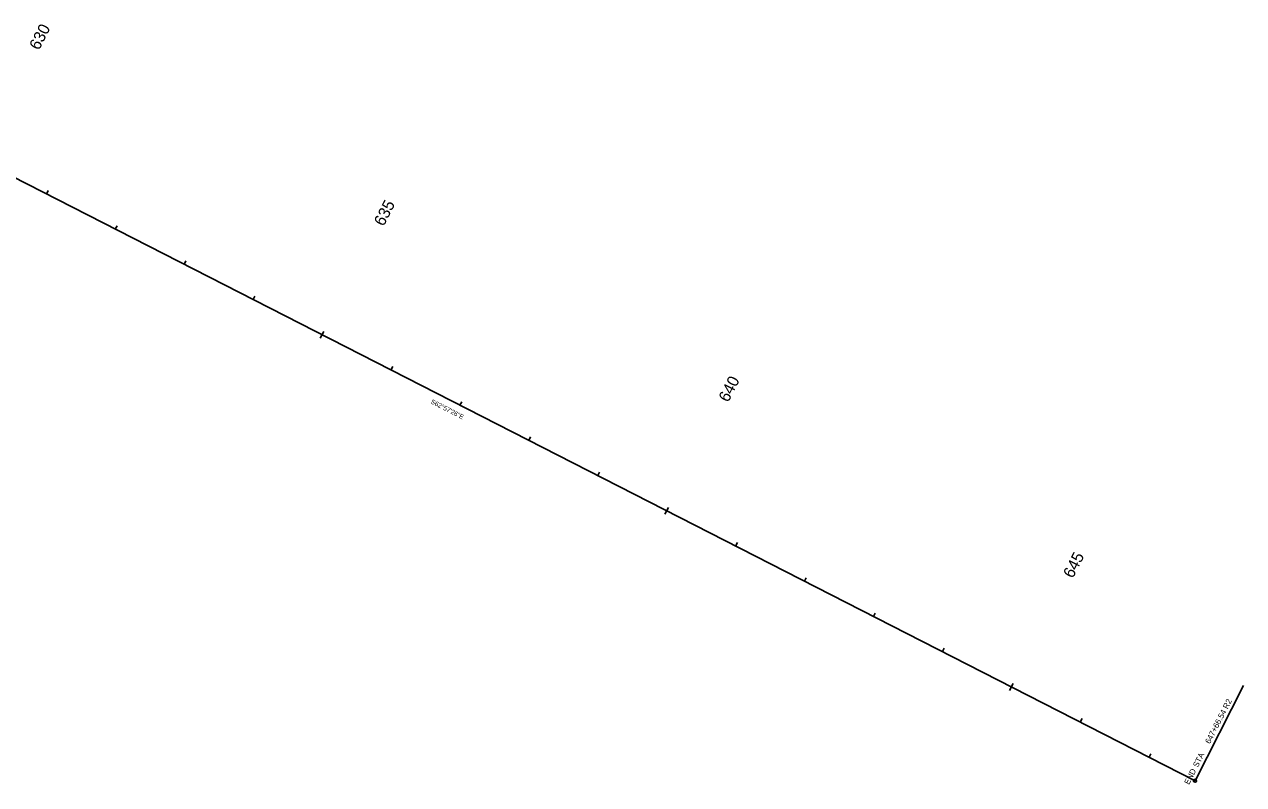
# Model space of a CAD drawing. Extents: x 1604865 to 1608475, y 865355 to 868094.
# Drawn here: x 1606900 to 1608475, y 865355 to 866336 of the extents above; entities that cross this region are included whole.
import ezdxf

# ---------------------------------------------------------------- set-up
doc = ezdxf.new("R2010")
doc.units = 0
for name, color, linetype in [('Default', 7, 'Continuous'), ('Modeling-Contours-Major-Existing', 7, 'Continuous'), ('Modeling-Contours-Minor-Existing', 7, 'Continuous'), ('Modeling-Flow Arrows-Existing', 7, 'Continuous'), ('Modeling-Low Points-Existing', 7, 'Continuous'), ('Modeling-Spot-Existing', 7, 'Continuous'), ('Modeling-Terrain-Existing', 7, 'Continuous'), ('Modeling-Triangle Verticies-Existing', 7, 'Continuous')]:
    doc.layers.add(name, color=color, linetype=linetype)

msp = doc.modelspace()

# ---------------------------------------------------------------- linework, layer by layer
at = {"layer": 'Default'}
msp.add_line((1606506.8, 866332.4), (1608412.4, 865359.6), dxfattribs=at)
at = {"layer": 'Modeling-Contours-Minor-Existing'}
for p, q in [((1607286.6, 865939.9), (1607282.1, 865931)), ((1607732, 865712.6), (1607727.4, 865703.7)), ((1608177.3, 865485.2), (1608172.7, 865476.3))]:
    msp.add_line(p, q, dxfattribs=at)
at = {"layer": 'Modeling-Spot-Existing'}
for p in [(1608412.4, 865359.6), (1608475.2, 865482.5)]:
    msp.add_line(p, (1608475.2, 865482.5), dxfattribs=at)
msp.add_circle((1608412.4, 865359.6), 1.98, dxfattribs=at)
at = {"layer": 'Modeling-Terrain-Existing'}
msp.add_line((1606506.8, 866332.4), (1608412.4, 865359.6), dxfattribs=at)
at = {"layer": 'Modeling-Triangle Verticies-Existing'}
for p, q in [((1606928.1, 866117.3), (1606930.4, 866121.8)), ((1607017.2, 866071.9), (1607019.4, 866076.3)), ((1607106.2, 866026.4), (1607108.5, 866030.8)), ((1607195.3, 865980.9), (1607197.6, 865985.4)), ((1607373.4, 865890), (1607375.7, 865894.4)), ((1607462.5, 865844.5), (1607464.8, 865849)), ((1607551.6, 865799.1), (1607553.8, 865803.5)), ((1607640.6, 865753.6), (1607642.9, 865758)), ((1607818.8, 865662.7), (1607821, 865667.1)), ((1607907.8, 865617.2), (1607910.1, 865621.7)), ((1607996.9, 865571.7), (1607999.2, 865576.2)), ((1608086, 865526.3), (1608088.2, 865530.7)), ((1608264.1, 865435.3), (1608266.4, 865439.8)), ((1608353.2, 865389.9), (1608355.4, 865394.3))]:
    msp.add_line(p, q, dxfattribs=at)

# ---------------------------------------------------------------- texts
at = {"layer": 'Modeling-Contours-Major-Existing'}
for s, p in [('630', (1606918.5, 866302.1)), ('635', (1607363.9, 866074.7)), ('640', (1607809.2, 865847.4)), ('645', (1608254.5, 865620.1))]:
    msp.add_text(s, height=15, rotation=62.9572, dxfattribs=at).set_placement(p)
at = {"layer": 'Modeling-Flow Arrows-Existing'}
for s, p in [('647+66.54 R2', (1608431.6, 865406.6)), (' STA ', (1608414.7, 865373.6)), ('END', (1608404.6, 865353.9))]:
    msp.add_text(s, height=7.5, rotation=62.9572, dxfattribs=at).set_placement(p)
at = {"layer": 'Modeling-Low Points-Existing'}
msp.add_text('S62°57\'26"E', height=6, rotation=332.9572, dxfattribs=at).set_placement((1607424.2, 865847.2))

doc.saveas('drawing.dxf')
